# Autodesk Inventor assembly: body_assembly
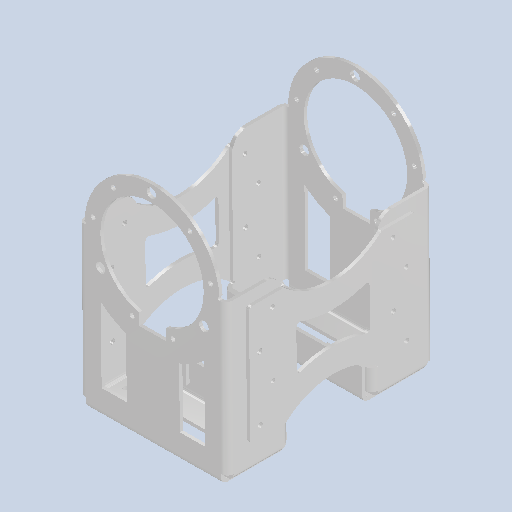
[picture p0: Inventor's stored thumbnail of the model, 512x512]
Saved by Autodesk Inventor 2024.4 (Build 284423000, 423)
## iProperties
Created: 2026-01
Part Number: body_assembly
Document SubType Name: Assembly
Designer: AdminForWorker
Title: body_assembly
Author: AdminForWorker
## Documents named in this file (3)
- c:\worker\convert-fusion-r06-cosv3\tmp\job-1\20\temp\files\5a45f03c-e7c3-4700-b116-8c6d3caf3368\body_assembly.iam
- c:\worker\convert-fusion-r06-cosv3\tmp\job-1\20\temp\files\5a45f03c-e7c3-4700-b116-8c6d3caf3368\front_body2.ipt
- c:\worker\convert-fusion-r06-cosv3\tmp\job-1\20\temp\files\5a45f03c-e7c3-4700-b116-8c6d3caf3368\front_body3.ipt
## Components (4 placed, 2 different names)
1. front_body2:1
2. front_body3:1
3. front_body2:2
4. front_body3:2
